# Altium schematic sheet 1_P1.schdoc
size 307 x 218 mm; Symbol: Drawing-Symbol_A4; Device: Drawing-Symbol_A4; @Project Name: FrogduinoR2; @Page Count: 1; @Update Date: 2026-05-13; @Create Date: 2026-05-09; @Schematic Name: Schematic2; @Page No: 1; @Page Name: P1; Company: EasyEDA.com; Version: V1.0; Page Size: A4; @Create Time: 14:04:10; @Update Time: 14:56:04; Width: 1170; Height: 825; Region Start: 1; X Region Count: 6; Y Region Count: 4; Blade Width: 10; Title Block Position: 3; @Board Name: PCB6
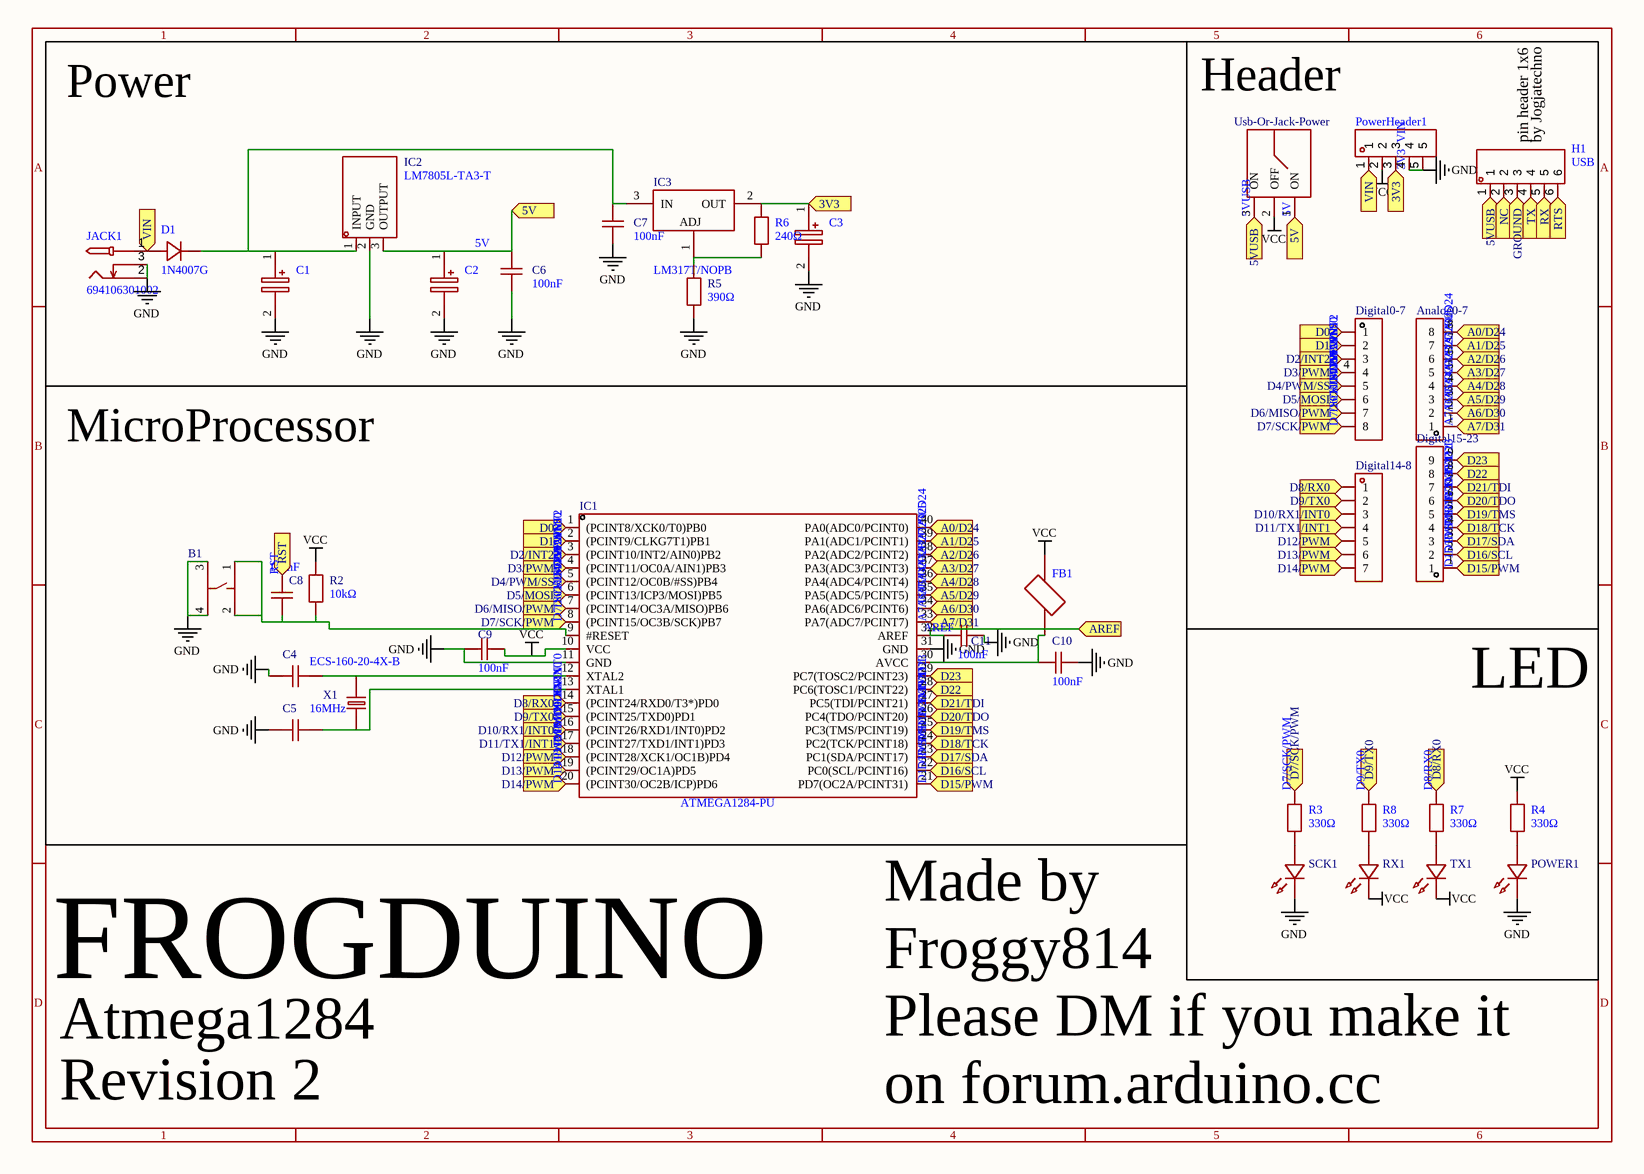
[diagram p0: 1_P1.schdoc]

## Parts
Analog0-7  排母HDR1X8-2.54  [HDR-TH_8P-P2.54-V-F]  (value not drawn)
B1  TS02-66-43-BK-100-SCR-D  [SW-TH_4P-L6.0-W6.0-P4.50-LS6.5]  (value not drawn)
C1  (no value)  [CAPPM7344X310N]
C2  (no value)  [CAPPM7344X310N]
C3  (no value)  [CAPPM7344X310N]
C4  C0805C220J4HACTU  [C1210]  (value not drawn)
C5  C0805C220J4HACTU  [C1210]  (value not drawn)
C6  100nF  [C1206]
C7  100nF  [C1206]
C8  100nF  [C1206]
C9  100nF  [C1206]
C10  100nF  [C1206]
C11  100nF  [C1206]
D1  1N4007G  [DO-41_BD2.4-L4.7-P8.70-D0.6-RD]
Digital0-7  排母HDR1X8-2.54  [HDR-TH_8P-P2.54-V-F]  (value not drawn)
Digital14-8  2.54-1*7P/30mm(3+24+3)  [HDR-TH_7P-P2.54-V-M-1]  (value not drawn)
Digital15-23  KH-2.54PH180-1X9P-L11.5  [HDR-TH_9P-P2.54-V-M]  (value not drawn)
FB1  (no value)  [FB_28L0138-70R-10]
H1  USB
IC1  ATMEGA1284-PU  [CONN-SMD_40P-P2.54_C9900007166]
IC2  LM7805L-TA3-T  [TO-220IS_L10.16-W4.7-P2.54-L]
IC3  LM317T/NOPB  [TO-220-3_L10.2-W4.6-P2.54-L]
JACK1  694106301002  [CONN-TH_694106301002]
POWER1  SML-811UTT86C  [LED-SMD_L3.4-W1.3-RD]  (value not drawn)
PowerHeader1  2.54mm1*5PHeader  [HDR-TH_5P-P2.54-V]  (value not drawn)
R2  10kΩ  [R2512]
R3  330Ω  [R2010]
R4  330Ω  [R2010]
R5  390Ω  [R2512]
R6  240Ω  [R2512]
R7  330Ω  [R2010]
R8  330Ω  [R2010]
RX1  SML-811UTT86C  [LED-SMD_L3.4-W1.3-RD]  (value not drawn)
SCK1  SML-811UTT86C  [LED-SMD_L3.4-W1.3-RD]  (value not drawn)
TX1  SML-811UTT86C  [LED-SMD_L3.4-W1.3-RD]  (value not drawn)
Usb-Or-Jack-Power  pu-mts-103 ON-OFF-ON  [SW-TH_MTS-103]  (value not drawn)
X1  16MHz  [HC-49US_L11.5-W4.5-P4.88]

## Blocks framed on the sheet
Power: C1-C3 C6 C7 D1 IC2 IC3 JACK1 R5 R6
Header: Analog0-7 Digital0-7 Digital14-8 Digital15-23 H1 PowerHeader1 Usb-Or-Jack-Power
MicroProcessor: B1 C4 C5 C8-C11 FB1 IC1 R2 X1
LED: POWER1 R3 R4 R7 R8 RX1 SCK1 TX1

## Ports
3V3 (in), 5V (in), 5VUSB (in), A0/D24 (in), A1/D25 (in), A2/D26 (in), A3/D27 (in), A4/D28 (in), A5/D29 (in), A6/D30 (in), A7/D31 (in), AREF (in), D0 (in), D1 (in), D2/INT2 (in), D3/PWM (in), D4/PWM/SS (in), D5/MOSI (in), D6/MISO/PWM (in), D7/SCK/PWM (in), D8/RX0 (in), D9/TX0 (in), D10/RX1/INT0 (in), D11/TX1/INT1 (in), D12/PWM (in), D13/PWM (in), D14/PWM (in), D15/PWM (in), D16/SCL (in), D17/SDA (in), D18/TCK (in), D19/TMS (in), D20/TDO (in), D21/TDI (in), D22 (in), D23 (in), GROUND (in), NC (in), RST (in), RTS (in), RX (in), TX (in), VIN (in)

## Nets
3V3: B1.3 B1.4 C1.2(-) C2.2(-) C3.2(-) C4.1 C5.1 C6.1 C7.1 C9.1 C10.2 C11.2 IC1.11(GND) IC1.31(GND) IC2.2(GND) JACK1.2 JACK1.3 POWER1.1(K) PowerHeader1.4 PowerHeader1.5 R5.1 SCK1.1(K)  [also labelled GND]
VCC: C9.2 FB1.2 IC1.10(VCC) PowerHeader1.2 R2.2 R4.2 RX1.1(K) TX1.1(K) Usb-Or-Jack-Power.2(OFF)
3V3: C3.1(+) IC3.2(OUT) PowerHeader1.3 R6.2 ; port 3V3  [a separate net that carries the same name]
5V: C2.1(+) C6.2 IC2.3(OUTPUT) Usb-Or-Jack-Power.1(ON) ; port 5V
5VUSB: H1.1 Usb-Or-Jack-Power.3(ON) ; port 5VUSB
A0/D24: Analog0-7.8 IC1.40(PA0(ADC0/PCINT0)) ; port A0/D24
A1/D25: Analog0-7.7 IC1.39(PA1(ADC1/PCINT1)) ; port A1/D25
A2/D26: Analog0-7.6 IC1.38(PA2(ADC2/PCINT2)) ; port A2/D26
A3/D27: Analog0-7.5 IC1.37(PA3(ADC3/PCINT3)) ; port A3/D27
A4/D28: Analog0-7.4 IC1.36(PA4(ADC4/PCINT4)) ; port A4/D28
A5/D29: Analog0-7.3 IC1.35(PA5(ADC5/PCINT5)) ; port A5/D29
A6/D30: Analog0-7.2 IC1.34(PA6(ADC6/PCINT6)) ; port A6/D30
A7/D31: Analog0-7.1 IC1.33(PA7(ADC7/PCINT7)) ; port A7/D31
AREF: C11.1 IC1.32(AREF) ; port AREF
D0: Digital0-7.7(1) IC1.1((PCINT8/XCK0/T0)PB0) ; port D0
D1: Digital0-7.6(2) IC1.2((PCINT9/CLKG7T1)PB1) ; port D1
D2/INT2: Digital0-7.5(3) IC1.3((PCINT10/INT2/AIN0)PB2) ; port D2/INT2
D3/PWM: Digital0-7.4 IC1.4((PCINT11/OC0A/AIN1)PB3) ; port D3/PWM
D4/PWM/SS: Digital0-7.3(5) IC1.5((PCINT12/OC0B/#SS)PB4) ; port D4/PWM/SS
D5/MOSI: Digital0-7.2(6) IC1.6((PCINT13/ICP3/MOSI)PB5) ; port D5/MOSI
D6/MISO/PWM: Digital0-7.1(7) IC1.7((PCINT14/OC3A/MISO)PB6) ; port D6/MISO/PWM
D7/SCK/PWM: Digital0-7.0(8) IC1.8((PCINT15/OC3B/SCK)PB7) R3.2 ; port D7/SCK/PWM
D8/RX0: Digital14-8.14(1) IC1.14((PCINT24/RXD0/T3*)PD0) R7.2 ; port D8/RX0
D9/TX0: Digital14-8.13(2) IC1.15((PCINT25/TXD0)PD1) R8.2 ; port D9/TX0
D10/RX1/INT0: Digital14-8.12(3) IC1.16((PCINT26/RXD1/INT0)PD2) ; port D10/RX1/INT0
D11/TX1/INT1: Digital14-8.11(4) IC1.17((PCINT27/TXD1/INT1)PD3) ; port D11/TX1/INT1
D12/PWM: Digital14-8.10(5) IC1.18((PCINT28/XCK1/OC1B)PD4) ; port D12/PWM
D13/PWM: Digital14-8.9(6) IC1.19((PCINT29/OC1A)PD5) ; port D13/PWM
D14/PWM: Digital14-8.8(7) IC1.20((PCINT30/OC2B/ICP)PD6) ; port D14/PWM
D15/PWM: Digital15-23.1 IC1.21(PD7(OC2A/PCINT31)) ; port D15/PWM
D16/SCL: Digital15-23.2 IC1.22(PC0(SCL/PCINT16)) ; port D16/SCL
D17/SDA: Digital15-23.3 IC1.23(PC1(SDA/PCINT17)) ; port D17/SDA
D18/TCK: Digital15-23.4 IC1.24(PC2(TCK/PCINT18)) ; port D18/TCK
D19/TMS: Digital15-23.5 IC1.25(PC3(TMS/PCINT19)) ; port D19/TMS
D20/TDO: Digital15-23.6 IC1.26(PC4(TDO/PCINT20)) ; port D20/TDO
D21/TDI: Digital15-23.7 IC1.27(PC5(TDI/PCINT21)) ; port D21/TDI
D22: Digital15-23.8 IC1.28(PC6(TOSC1/PCINT22)) ; port D22
D23: Digital15-23.9 IC1.29(PC7(TOSC2/PCINT23)) ; port D23
GROUND: H1.3 ; port GROUND
NC: H1.2 ; port NC
RST: C8.2 ; port RST
RTS: H1.6 ; port RTS
RX: H1.5 ; port RX
TX: H1.4 ; port TX
VIN: D1.2(A) JACK1.1 PowerHeader1.1 ; port VIN
NetB1_1: B1.1 B1.2 C8.1 IC1.9(#RESET) R2.1
NetC1_1: C1.1(+) C7.2 D1.1(K) IC2.1(INPUT) IC3.3(IN)
NetC4_2: C4.2 IC1.12(XTAL2) X1.2
NetC5_2: C5.2 IC1.13(XTAL1) X1.1
NetC10_1: C10.1 FB1.1 IC1.30(AVCC)
NetIC3_1: IC3.1(ADJ) R5.2 R6.1
NetPOWER1_2: POWER1.2(A) R4.1
NetR3_1: R3.1 SCK1.2(A)
NetR7_1: R7.1 TX1.2(A)
NetR8_1: R8.1 RX1.2(A)

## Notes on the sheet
- (near C4) ECS-160-20-4X-B
- Made by
  Froggy814
  Please DM if you make it
  on forum.arduino.cc
- FROGDUINO
- Atmega1284
- Revision 2
- Labels drawn without touching a wire or pin: AREF, VIN

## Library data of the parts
Analog0-7 Digital0-7 = 排母HDR1X8-2.54: Add into BOM: yes
B1 = TS02-66-43-BK-100-SCR-D: Manufacturer: CUI; Add into BOM: yes; Circuit: SPST; Actuator Style: Round Button; Operating Force: 1N; Contact Current: 50mA; Voltage Rating: 12V; Life: 100,000 Cycles
C1-C3 = TAJD107K016SNJV_: Add into BOM: yes
C4 C5 = C1210C220J5GACTU: Add into BOM: yes
C6-C11 = 1206B104K101CT: Manufacturer: Walsin(华新科); Add into BOM: yes; Tolerance: ±10%; Voltage Rating: 100V; Temperature Coefficient: X7R
D1 = 1N4007G: Symbol: 1N4007G_C2764732; Add into BOM: yes; Forward Voltage (Vf@If): 1.1V@1A; Reverse Leakage Current: 5uA@1kV
Digital14-8 = 2.54-1*7P/30mm(3+24+3): Add into BOM: yes
Digital15-23 = KH-2.54PH180-1X9P-L11.5: Manufacturer: kinghelm(金航标); Add into BOM: yes; Pin Structure: 1x9P; Pitch: 2.54mm; Circluar Pins/Square Pins: Policy; Current Rating: 3A
FB1 = 28L0138-70R-10_: Add into BOM: yes
H1 = Headers  Pins1x6P 2.54mm: Manufacturer: ReliaPro; Add into BOM: yes
IC1 = ATMEGA1284-PU: Manufacturer: MICROCHIP(美国微芯); Add into BOM: yes; CPU Core: AVR; CPU Maximum Speed: 20MHz; Program Storage Size: 128KB; Program Memory Type: FLASH; EEPROM: 4KB; Number of I/O: 32; ADC (Bit): 10bit; Voltage - Supply: 1.8V~5.5V
IC2 = LM7805L-TA3-T: Symbol: LM7805L-TA3-T_C340686; Add into BOM: yes
IC3 = LM317T/NOPB: Manufacturer: TI(德州仪器); Add into BOM: yes; Output Type: Adjustable; Voltage - Supply: 40V; Output Voltage: 1.25V~37V; Output Current: 1.5A; Power Supply Rejection Ratio (PSRR): 80dB@(120Hz); standby current: 50uA; Output Configuration: Positive; Number of Outputs: 1
JACK1 = 694106301002: Manufacturer: würth Elektronik; Add into BOM: yes
POWER1 RX1 SCK1 TX1 = SML-811UTT86C: Manufacturer: ROHM(罗姆); Add into BOM: yes; Illumination Color: Red; Voltage - Forward(Vf): 1.95V; Forward Current: 10mA; Wavelength - Dominant: 620nm; Lens Color: Water Clear; Luminous Intensity: 22.4mcd
PowerHeader1 = 2.54mm 1*5P Header: Manufacturer: ReliaPro; Symbol: 2&quot;42 OLED - DIY More; Convert to PCB: yes
R2 = AS25J1002ET: Manufacturer: Ohmite; Add into BOM: yes; Tolerance: ±5%; Power(Watts): 1.5W; Temperature Coefficient: ±100ppm/℃
R3 R4 R7 R8 = RC2010JK-07330RL: Manufacturer: YAGEO(国巨); Add into BOM: yes; Tolerance: ±5%; Temperature Coefficient: ±100ppm/℃
R5 = CRGP2512F390R: Manufacturer: TE Connectivity(泰科电子); Add into BOM: yes; Tolerance: ±1%; Temperature Coefficient: ±100ppm/℃
R6 = RK73H3ATTE2400F: Manufacturer: KOA; Add into BOM: yes; Tolerance: ±1%; Power(Watts): 1W; Temperature Coefficient: ±100ppm/℃
Usb-Or-Jack-Power = pu-mts-103 ON-OFF-ON: Add into BOM: yes
X1 = XIHCELNANF-16MHZ: Manufacturer: TAITIEN(泰艺电子); Add into BOM: yes; Normal temperature Frequency Tolerance: ±30ppm; Load Capacitance: 20pF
